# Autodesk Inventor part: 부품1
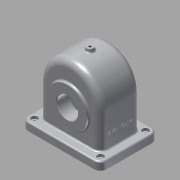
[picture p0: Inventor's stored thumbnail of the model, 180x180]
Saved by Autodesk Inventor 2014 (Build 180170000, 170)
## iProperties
Created: 2016-10
Part Number: 부품1
Material: 알루미늄 6061
Document SubType Name: Modeling
Designer: SCD-A13
Density: 2.71 g/cm^3
Appearance: 알루미늄 - 평지
Mass: 1172.89 g
Surface Area: 1200.96 cm^2
Volume: 432.802 cm^3
Author: SCD-A13
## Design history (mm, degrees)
sketch "스케치1"
  geometry: L1 (75, 55)-(-75, 55); L2 (-75, 55)-(-75, -55); L3 (-75, -55)-(75, -55); L4 (75, -55)-(75, 55); L5 (75, 55)-(-75, -55); L6 (-75, 55)-(75, -55); 1 further point
  constraints: 12 end point, 2 midpoint, 2 parallel, 1 horizontal, 1 perpendicular
  dimensions: "d0" = 150 distance of L2.end L3.end; "d1" = 110 distance of L3.end L1.start
extrude "돌출1" new body sketch "스케치1" distance "d2" = 15; taper "d3" = 0 deg
sketch "스케치2"
  geometry: L1 (75, 15)-(-75, 15) reference; L2 (-58, 80)-(-58, 15); L3 (-75, 0)-(-75, 15) reference; L4 (58, 80)-(58, 15); L5 (75, 0)-(-75, 0) reference; A1 r 58 centre (0, 80) between (-58, 80) and (58, 80); 2 further points
  constraints: 4 end point, 2 point on circle, 2 point on line, 2 tangent, 1 centre point, 1 midpoint, 1 parallel, 1 perpendicular, 1 vertical alignment
  dimensions: "d4" = 116 diameter of A1; "d5" = 80 distance from line of L5 A1.centre
extrude "돌출2" join sketch "스케치2" stored distance "d6" = 77; taper "d7" = 0 deg
fillet "모깎기1" dims "d8" = 13
sketch "스케치3"
  geometry: L1 (52, 80)-(52, 0); L2 (-52, 80)-(-52, 0); L3 (-58, 15)-(-58, 80) reference; L4 (-52, 0)-(52, 0); L5 (75, 0)-(-75, 0) reference; A1 r 52 centre (0, 80) between (52, 80) and (-52, 80); A2 r 58 centre (0, 80) between (58, 80) and (-58, 80) reference; 1 further point
  constraints: 6 end point, 2 point on circle, 2 tangent, 1 centre point, 1 coincident, 1 collinear, 1 parallel, 1 perpendicular, 1 vertical, 1 vertical alignment
  dimensions: "d9" = 104 diameter of A1
extrude "돌출3" cut sketch "스케치3" stored distance "d11" = 67; taper "d12" = 0 deg
fillet "모깎기2" dims "d13" = 8
node "작업 평면1"
sketch "스케치4"
  geometry: C1 r 28 at (0, 65); 1 further point
  constraints: 1 centre point
  dimensions: "d15" = 56 diameter of C1; "d16" = 65 distance of point (0, 0) C1.centre
extrude "돌출4" join sketch "스케치4" stored distance "d17" = 67; taper "d18" = 40 deg
sketch "스케치5"
  geometry: L1 (-75, 0)-(75, 0) reference; C1 r 37.5 at (0, 65); 1 further point
  constraints: 1 centre point
  dimensions: "d19" = 75 diameter of C1; "d20" = 65 distance from line of L1 C1.centre
extrude "돌출5" join sketch "스케치5" distance "d21" = 5; taper "d22" = 0 deg
sketch "스케치6"
  geometry: L1 (-75, 0)-(75, 0) reference; C1 r 32.5 at (0, 65); 1 further point
  constraints: 1 centre point
  dimensions: "d23" = 65 diameter of C1; "d24" = 65 distance from line of L1 C1.centre
extrude "돌출6" join sketch "스케치6" distance "d25" = 10; taper "d26" = 0 deg
hole "구멍1" diameter "d29" = 40; stored, may be unused: countersink angle "d33" = 90 deg, drill point angle "d35" = 118 deg; dims "d27" = 10, "d28" = 10, "d30" = 6, "d31" = 4, "d32" = 2, "d34" = 8
node "작업 평면2"
sketch "스케치8"
  geometry: C1 r 6 at (0, 0); 1 further point
  constraints: 1 centre point, 1 coincident
  dimensions: "d37" = 12 diameter of C1
extrude "돌출7" join sketch "스케치8" stored distance "d38" = 10; taper "d39" = 10 deg
fillet "모깎기3" dims "d40" = 3
hole "구멍2" diameter "d43" = 4.459; stored, may be unused: countersink angle "d47" = 90 deg, drill point angle "d49" = 118 deg; dims "d41" = 10, "d42" = 10, "d44" = 6, "d45" = 4, "d46" = 2, "d48" = 8
chamfer "모따기1" distance "d50" = 1; stored, may be unused: second distance "d51" = 2, angle "d52" = 45 deg
fillet "모깎기4" dims "d53" = 12
fillet "모깎기5" dims "d54" = 3
sketch "스케치9"
  geometry: A1 r 9 centre (-63, 43) between (-63, 52) and (-72, 43) reference; A2 r 9 centre (-63, -43) between (-72, -43) and (-63, -52) reference; A3 r 9 centre (63, -43) between (63, -52) and (72, -43) reference; A4 r 9 centre (63, 43) between (72, 43) and (63, 52) reference; 5 further points
  constraints: 4 coincident
hole "구멍3" sketch "스케치9" at (-63, 43), (63, 43), (63, -43), (-63, -43) diameter "d55" = 5; stored, may be unused: countersink angle "d59" = 90 deg, drill point angle "d61" = 118 deg; dims "d56" = 6, "d57" = 12, "d58" = 5, "d60" = 8
sketch "스케치10" dims "d62" = 52
  geometry: C1 r 32.5 at (0, 0) reference; C2 r 21 at (0, 0) reference; 3 further points
  constraints: 2 vertical alignment, 1 coincident, 2 other
hole "구멍4" sketch "스케치10" at (0, 26) diameter "d63" = 2.459; stored, may be unused: countersink angle "d67" = 90 deg, drill point angle "d69" = 118 deg; dims "d64" = 6, "d65" = 12, "d66" = 5, "d68" = 8
sketch "스케치11" dims "d73" = 58
  geometry: C1 r 37.5 at (0, 0) reference; C2 r 21 at (0, 0) reference; 3 further points
  constraints: 2 vertical alignment, 1 coincident, 2 other
hole "구멍5" sketch "스케치11" at (0, 29) diameter "d74" = 2.459; stored, may be unused: countersink angle "d78" = 90 deg, drill point angle "d80" = 118 deg; dims "d75" = 6, "d76" = 12, "d77" = 5, "d79" = 8
sketch "스케치12"
  geometry: L1 (-17.5, -80)-(-29.5, -80) reference; L2 (-13, 0)-(-13, -62) reference; 2 further points
  constraints: 1 other
  dimensions: "d84" = 40 distance from line of L1 point (25.5, -40); "d85" = 38.5 distance from line of L2 point (25.5, -40)
feature "엠보싱1" sketch "스케치12" dims "d0" = 150, "d1" = 110, "d8" = 13, "d86" = 0.5, "d87" = 0
node "솔리드1"
pattern_circular "원형 패턴1" dims angle "d71" = 360 deg
pattern_circular "원형 패턴2" dims angle "d82" = 360 deg
other parameters: "d14" = 14, "d36" = 144
